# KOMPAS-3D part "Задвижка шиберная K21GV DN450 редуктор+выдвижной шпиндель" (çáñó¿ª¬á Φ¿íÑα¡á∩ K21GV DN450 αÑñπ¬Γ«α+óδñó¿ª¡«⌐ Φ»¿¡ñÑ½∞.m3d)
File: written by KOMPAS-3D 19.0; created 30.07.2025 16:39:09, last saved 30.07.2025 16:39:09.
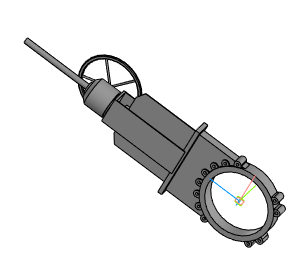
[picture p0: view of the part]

Document properties: Полное имя файла: Задвижка шиберная K21GV DN450 редуктор+выдвижной шпиндель.a3d

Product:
- Part/product: Задвижка шиберная K21GV DN450 редуктор+выдвижной шпиндель
    Масса: 203.897

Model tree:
1. Операция без истории:1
